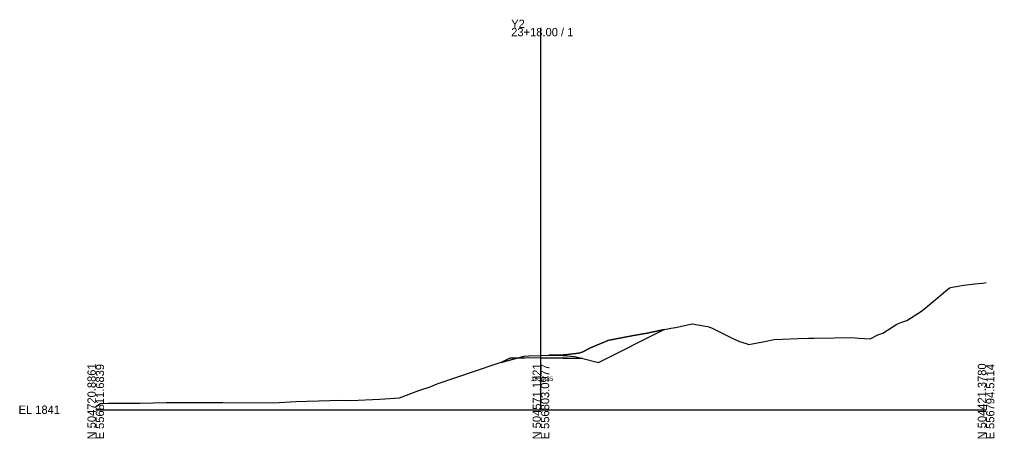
# Model space of a CAD drawing. Extents: x -26 to 1503, y -10 to 3574.
# Drawn here: x 1174.3 to 1502.8, y -9.7 to 131.5 of the extents above; entities that cross this region are included whole.
import ezdxf

# ---------------------------------------------------------------- set-up
doc = ezdxf.new("R2010")
doc.units = 0
for name, color, linetype in [('Exist Cross Section Cell', 7, 'Continuous'), ('Exist XS Ground Line', 7, 'Continuous'), ('Prop CMT Subgrade Earthwork', 7, 'Continuous'), ('Prop XS Ditch Standard Text', 7, 'Continuous'), ('Prop XS Earthwork Shape', 7, 'Continuous')]:
    doc.layers.add(name, color=color, linetype=linetype)

msp = doc.modelspace()

# ---------------------------------------------------------------- linework, layer by layer
at = {"layer": 'Exist Cross Section Cell'}
for p, q in [((1350, 0), (1350, 128.61)), ((1200, 0), (1350, 0)), ((1350, 0), (1500, 0))]:
    msp.add_line(p, q, dxfattribs=at)
at = {"layer": 'Exist XS Ground Line'}
msp.add_lwpolyline([(1200, 1.07), (1201.62, 2.08), (1204.28, 2.21), (1214.95, 2.23), (1223.78, 2.38), (1241.17, 2.44), (1241.96, 2.42), (1242.82, 2.4), (1259.89, 2.31), (1267.45, 2.79), (1282.69, 3.27), (1285.9, 3.16), (1295.74, 3.53), (1302.32, 3.97), (1308.89, 6.45), (1312.72, 7.67), (1315.06, 8.71), (1334.62, 15.39), (1335.89, 15.76), (1336.25, 15.86), (1344.41, 18.07), (1345.94, 18.14), (1350, 18.25), (1356.41, 18.43), (1357.66, 18.48), (1358.99, 18.63), (1362.71, 19.07), (1363.93, 19.4), (1366.67, 20.87), (1371, 22.66), (1372.15, 23.15), (1372.51, 23.3), (1373.02, 23.39), (1374.19, 23.61), (1381.2, 24.96), (1385.76, 25.75), (1393.79, 27.47), (1395.39, 27.75), (1400.99, 28.96), (1405.41, 28.17), (1406.23, 27.99), (1406.77, 27.86), (1407.47, 27.6), (1414.47, 24.07), (1416.86, 23.01), (1419.15, 22.34), (1420.11, 21.99), (1425.39, 23.03), (1428.61, 23.65), (1431.38, 23.75), (1436.68, 23.95), (1440.22, 24.08), (1442.03, 24.16), (1448.78, 24.22), (1454.67, 24.3), (1457.11, 24.14), (1460.98, 23.83), (1463.52, 25.23), (1465.2, 25.78), (1469.91, 28.84), (1471.62, 29.48), (1473.26, 30.09), (1478.25, 33.22), (1479.47, 34.16), (1482.89, 36.99), (1487.71, 41.08), (1488.61, 41.25), (1492.49, 41.91), (1496.22, 42.37), (1498.77, 42.69), (1500, 42.87)], dxfattribs=at)
at = {"layer": 'Prop CMT Subgrade Earthwork'}
msp.add_line((1343.23, 17.37), (1339.56, 17.42), dxfattribs=at)
for points in [[(1344.62, 17.4), (1343.23, 17.37)], [(1350, 17.5), (1344.62, 17.4)], [(1350, 17.5), (1357.4, 17.36)], [(1357.4, 17.36), (1358.79, 17.33)], [(1358.79, 17.33), (1364.16, 17.22)]]:
    msp.add_lwpolyline(points, dxfattribs=at)
at = {"layer": 'Prop XS Earthwork Shape'}
for points in [[(1357.4, 18.23), (1361.4, 17.91), (1364.16, 17.22), (1369.4, 15.91), (1391.55, 26.99), (1385.76, 25.75), (1381.2, 24.96), (1374.19, 23.61), (1373.02, 23.39), (1372.51, 23.3), (1372.15, 23.15), (1371, 22.66), (1366.67, 20.87), (1363.93, 19.4), (1362.71, 19.07), (1358.99, 18.63), (1357.66, 18.48), (1356.41, 18.43), (1352.7, 18.33)], [(1336.64, 15.96), (1341.9, 17.39), (1339.56, 17.42)], [(1344.62, 17.4), (1343.23, 17.37), (1341.9, 17.39), (1344.41, 18.07), (1345.94, 18.14), (1350, 18.25), (1352.7, 18.33), (1357.4, 18.23), (1361.4, 17.91), (1364.16, 17.22), (1358.79, 17.33), (1357.4, 17.36), (1350, 17.5)]]:
    msp.add_lwpolyline(points, close=True, dxfattribs=at)

# ---------------------------------------------------------------- texts
at = {"layer": 'Exist Cross Section Cell'}
for s, p in [('Y2', (1340, 128.61)), ('23+18.00 / 1', (1340, 125.81)), ('EL 1841', (1174, -1.4))]:
    msp.add_text(s, height=2.8, dxfattribs=at).set_placement(p)
for s, p in [('N 504720.8861', (1200, -10)), ('E 556811.6839', (1202.8, -10)), ('N 504571.1321', (1350, -10)), ('E 556803.0977', (1352.8, -10)), ('N 504421.3780', (1500, -10)), ('E 556794.5114', (1502.8, -10))]:
    msp.add_text(s, height=2.8, rotation=90, dxfattribs=at).set_placement(p)
at = {"layer": 'Prop XS Ditch Standard Text'}
msp.add_text('1859.25', height=1.5, dxfattribs=at).set_placement((1346.66, 9.69))

doc.saveas('drawing.dxf')
